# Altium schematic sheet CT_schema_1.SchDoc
size 289 x 339 mm
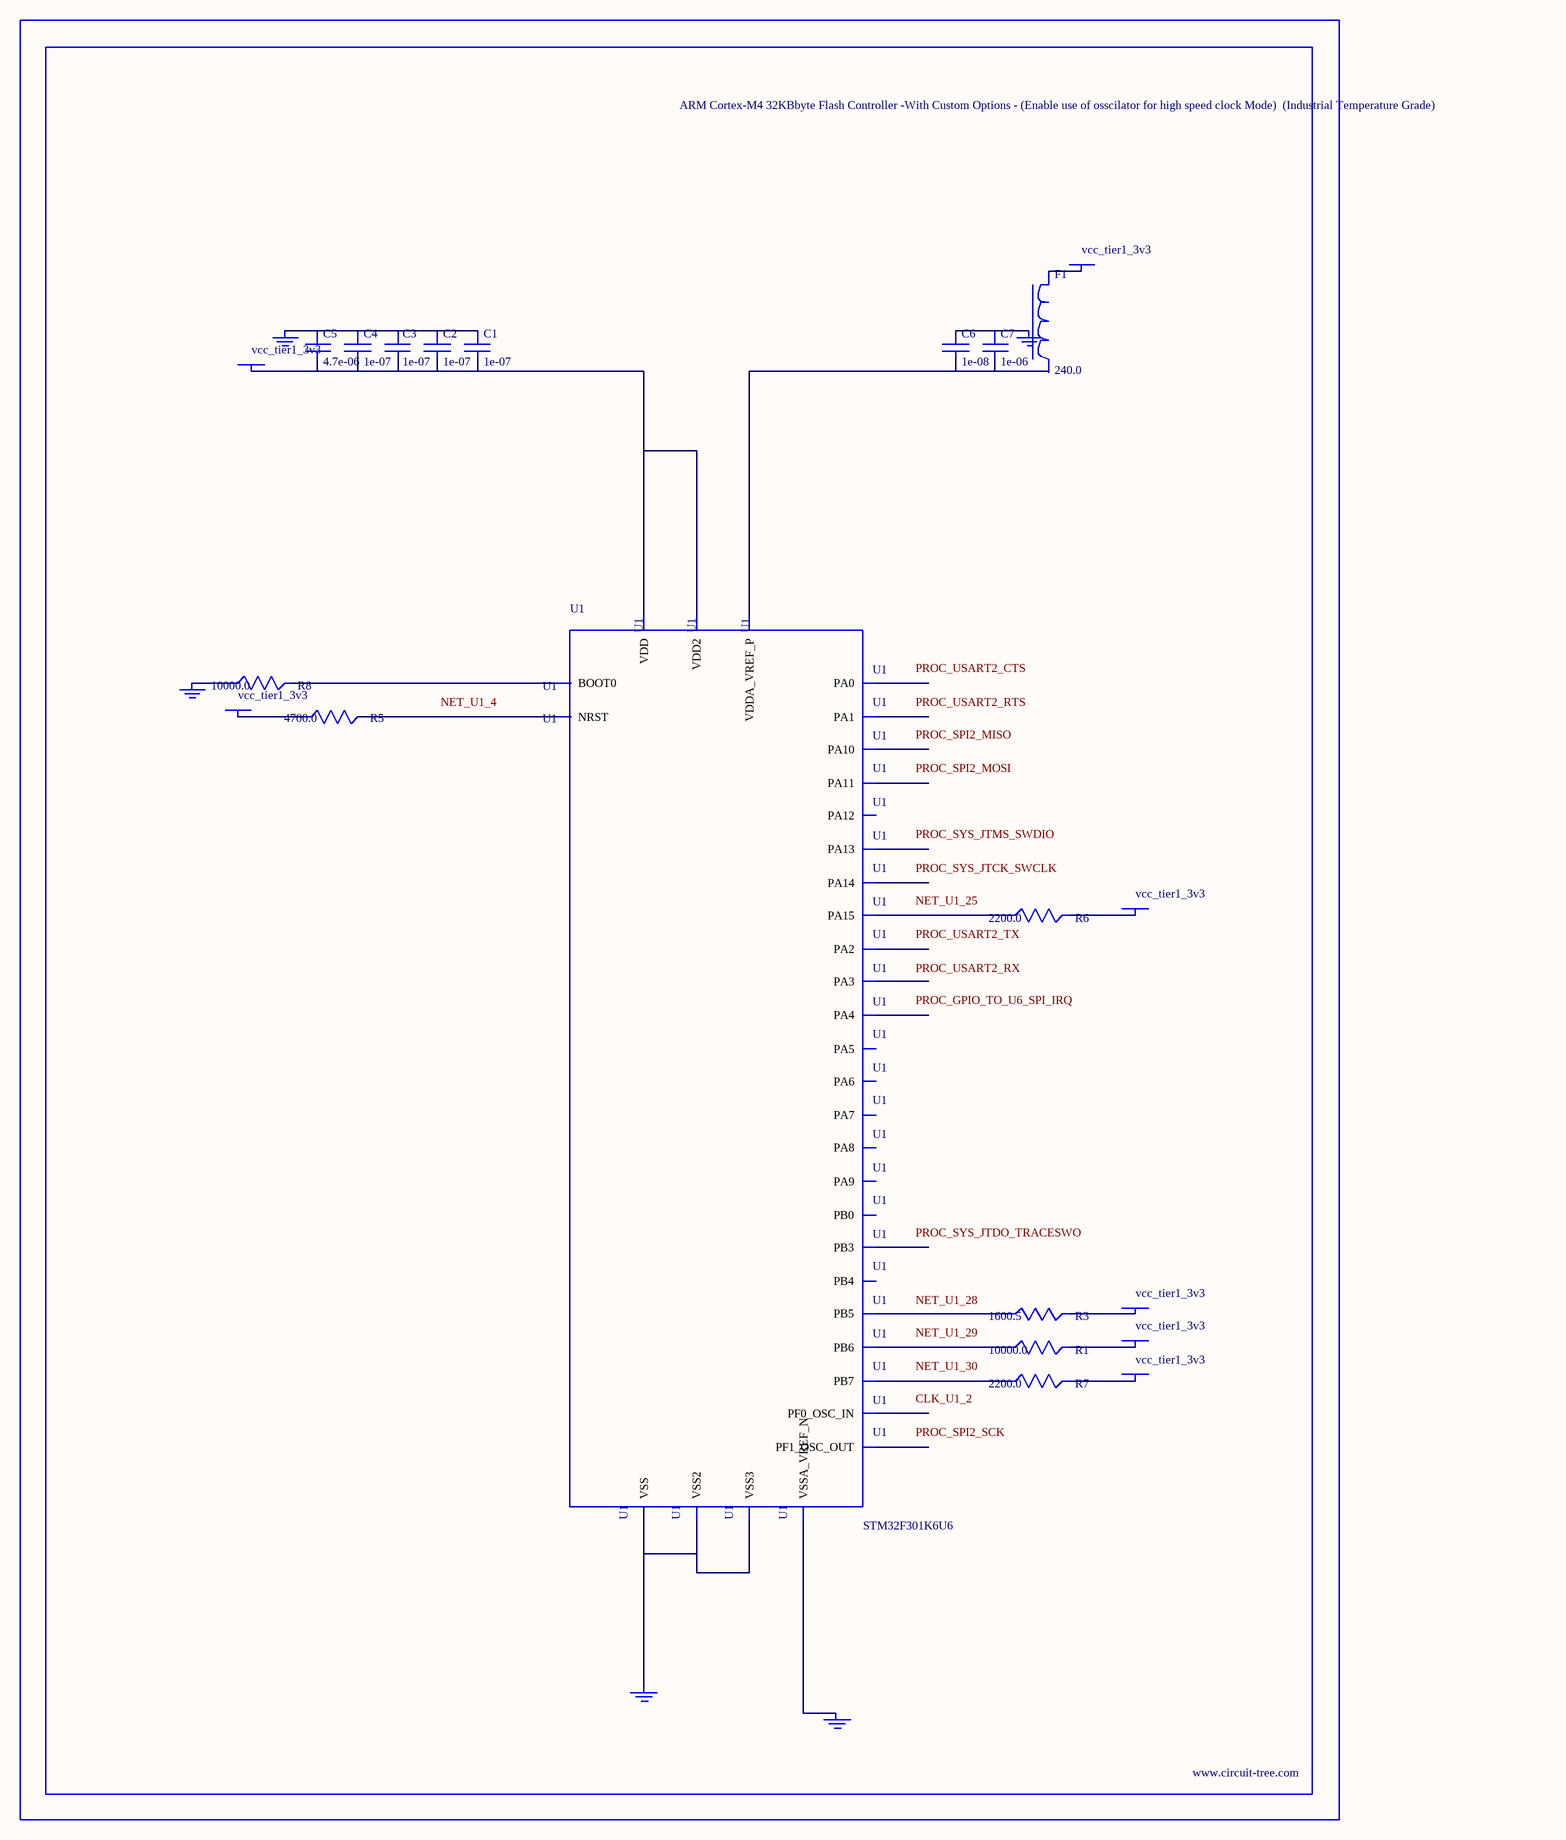
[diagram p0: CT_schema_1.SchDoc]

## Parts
BORDER0  (no value)
C1  1e-07  [C0603]
C2  1e-07  [C0603]
C3  1e-07  [C0603]
C4  1e-07  [C0603]
C5  4.7e-06  [C0603]
C6  1e-08  [C0603]
C7  1e-06  [C0603]
F1  240.0  [L0603]
GND_INSTANCE_0_0  (no value)
GND_INSTANCE_0_1  (no value)
GND_INSTANCE_0_2  (no value)
GND_INSTANCE_0_3  (no value)
GND_INSTANCE_0_4  (no value)
POWER_INSTANCE_0_0  vcc_tier1_3v3
POWER_INSTANCE_0_1  vcc_tier1_3v3
POWER_INSTANCE_0_2  vcc_tier1_3v3
POWER_INSTANCE_0_3  vcc_tier1_3v3
POWER_INSTANCE_0_4  vcc_tier1_3v3
POWER_INSTANCE_0_5  vcc_tier1_3v3
POWER_INSTANCE_0_6  vcc_tier1_3v3
R1  10000.0  [R0603]
R3  1600.5  [R0603]
R5  4700.0  [R0603]
R6  2200.0  [R0603]
R7  2200.0  [R0603]
R8  10000.0  [R0603]
U1  STM32F301K6U6  [UFQFPN32]

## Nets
NetC1_1: C1.1 C2.1 C3.1 C4.1 C5.1 GND_INSTANCE_0_0.0(GND)
NetC1_2: C1.2 C2.2 C3.2 C4.2 C5.2 POWER_INSTANCE_0_0.0(PWR) U1.1(VDD) U1.17(VDD2)
NetC6_1: C6.1 C7.1 GND_INSTANCE_0_1.0(GND)
NetC6_2: C6.2 C7.2 U1.5(VDDA_VREF_P)
NetF1_1: F1.1 POWER_INSTANCE_0_1.0(PWR)
NetGND_INSTANCE_0_2_0: GND_INSTANCE_0_2.0(GND) U1.6(VSSA_VREF_N)
NetGND_INSTANCE_0_3_0: GND_INSTANCE_0_3.0(GND) R8.1
NetGND_INSTANCE_0_4_0: GND_INSTANCE_0_4.0(GND) U1.16(VSS) U1.32(VSS2) U1.EPAD(VSS3)
NetPOWER_INSTANCE_0_2_0: POWER_INSTANCE_0_2.0(PWR) R5.1
NetPOWER_INSTANCE_0_3_0: POWER_INSTANCE_0_3.0(PWR) R6.2
NetPOWER_INSTANCE_0_4_0: POWER_INSTANCE_0_4.0(PWR) R3.2
NetPOWER_INSTANCE_0_5_0: POWER_INSTANCE_0_5.0(PWR) R1.2
NetPOWER_INSTANCE_0_6_0: POWER_INSTANCE_0_6.0(PWR) R7.2
NetR1_1: R1.1 U1.29(PB6)
NetR3_1: R3.1 U1.28(PB5)
NetR5_2: R5.2 U1.4(NRST)
NetR6_1: R6.1 U1.25(PA15)
NetR7_1: R7.1 U1.30(PB7)
NetR8_2: R8.2 U1.31(BOOT0)

Not connected (* = marked no-connect by the designer): F1 2; U1 2(PF0_OSC_IN) 3(PF1_OSC_OUT) 7(PA0) 8(PA1) 9(PA2) 10(PA3) 11(PA4) 12(PA5) 13(PA6) 14(PA7) 15(PB0) 18(PA8) 19(PA9) 20(PA10) 21(PA11) 22(PA12) 23(PA13) 24(PA14) 26(PB3) 27(PB4)

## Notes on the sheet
- Labels drawn without touching a wire or pin: CLK_U1_2, NET_U1_4, NET_U1_25, NET_U1_28, NET_U1_29, NET_U1_30, PROC_GPIO_TO_U6_SPI_IRQ, PROC_SPI2_MISO, PROC_SPI2_MOSI, PROC_SPI2_SCK, PROC_SYS_JTCK_SWCLK, PROC_SYS_JTDO_TRACESWO, PROC_SYS_JTMS_SWDIO, PROC_USART2_CTS, PROC_USART2_RTS, PROC_USART2_RX, PROC_USART2_TX

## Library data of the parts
BORDER0 = BORDER_PAGE0
C1-C4 = 06035C104K4Z2A
C5 = GRM188R6YA475KE15D
C6 = 06035C103K4Z2A
C7 = C0603C105K3RACTU
F1 = Z0603C241ASMST
GND_INSTANCE_0_0-GND_INSTANCE_0_4 = GND
POWER_INSTANCE_0_0-POWER_INSTANCE_0_6 = PWR
R1 R8 = RC0603JR-0710KL
R3 = R3
R5 = RC0603JR-074K7L
R6 R7 = RC0603JR-072K2L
